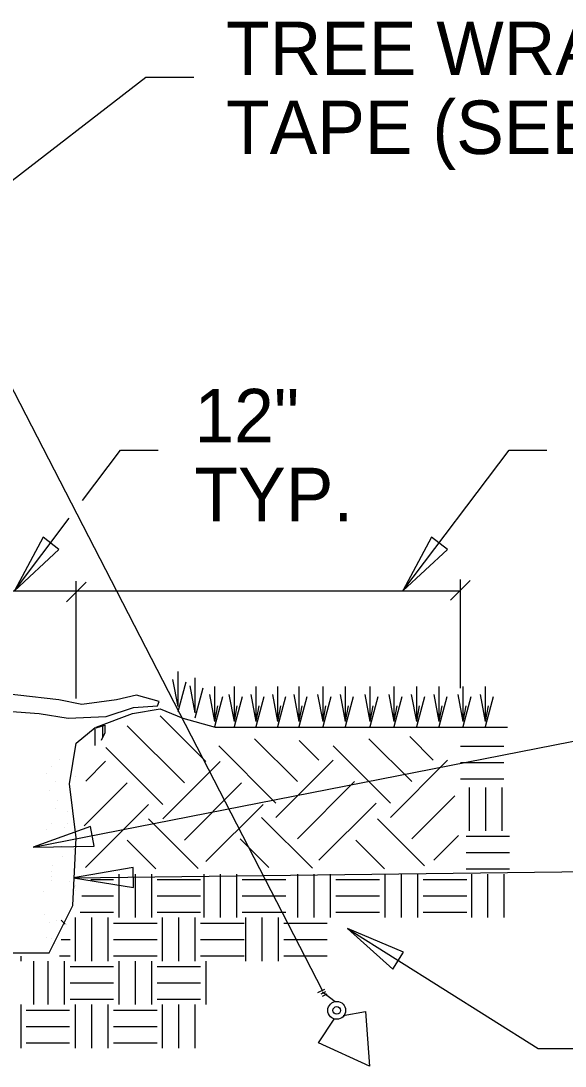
# Model space of a CAD drawing. Extents: x 10082 to 10241, y 10014 to 10069.
# Drawn here: x 10140.48 to 10147.61, y 10021.71 to 10035.4 of the extents above; entities that cross this region are included whole.
import ezdxf

# ---------------------------------------------------------------- set-up
doc = ezdxf.new("R2010")
doc.units = 0
for name, color, linetype in [('Default', 7, 'Continuous'), ('G-DETL-LINE', 7, 'Continuous'), ('G-DETL-OTLN', 7, 'Continuous'), ('G-DETL-PATT', 7, 'Continuous'), ('G-DETL-TEXT', 7, 'Continuous')]:
    doc.layers.add(name, color=color, linetype=linetype)

msp = doc.modelspace()

# ---------------------------------------------------------------- linework, layer by layer
at = {"layer": 'Default'}
for p, q in [((10137.692, 10031.254), (10142.113, 10034.665)), ((10142.113, 10034.665), (10142.742, 10034.665)), ((10141.285, 10029.12), (10141.783, 10029.78)), ((10141.783, 10029.78), (10142.277, 10029.78)), ((10145.484, 10027.939), (10146.875, 10029.78)), ((10146.875, 10029.78), (10147.369, 10029.78)), ((10140.393, 10027.939), (10141.11, 10028.888)), ((10141.204, 10026.527), (10141.204, 10028.065)), ((10146.108, 10027.818), (10146.366, 10028.075)), ((10141.075, 10027.795), (10141.333, 10028.053)), ((10141.64, 10027.938), (10146.237, 10027.938)), ((10141.451, 10025.911), (10141.451, 10026.147)), ((10141.462, 10026.146), (10141.579, 10026.179)), ((10141.552, 10026.024), (10141.552, 10026.171)), ((10141.579, 10026.179), (10141.579, 10026.079)), ((10140.64, 10024.579), (10147.95, 10026.014)), ((10141.579, 10026.079), (10141.528, 10025.977)), ((10140.882, 10025.632), (10140.882, 10025.632)), ((10140.98, 10025.725), (10140.98, 10025.725)), ((10140.812, 10025.543), (10140.812, 10025.543)), ((10141.124, 10025.479), (10141.124, 10025.479)), ((10141.195, 10025.512), (10141.195, 10025.512)), ((10140.853, 10025.322), (10140.853, 10025.322)), ((10140.927, 10025.436), (10140.927, 10025.436)), ((10140.951, 10025.198), (10140.951, 10025.198)), ((10140.928, 10025.081), (10140.928, 10025.081)), ((10141.09, 10025.053), (10141.09, 10025.053)), ((10140.813, 10024.814), (10140.813, 10024.814)), ((10140.883, 10024.885), (10140.883, 10024.885)), ((10141.055, 10024.836), (10141.055, 10024.836)), ((10141.082, 10024.892), (10141.082, 10024.892)), ((10141.188, 10024.777), (10141.188, 10024.777)), ((10141.196, 10024.765), (10141.196, 10024.765)), ((10141.011, 10024.596), (10141.011, 10024.596)), ((10141.167, 10024.544), (10141.167, 10024.544)), ((10141.029, 10024.455), (10141.029, 10024.455)), ((10140.878, 10024.259), (10140.878, 10024.259)), ((10140.888, 10024.335), (10140.888, 10024.335)), ((10141.166, 10024.178), (10148.614, 10024.272)), ((10141.18, 10024.306), (10141.18, 10024.306)), ((10140.883, 10024.138), (10140.883, 10024.138)), ((10140.885, 10024.203), (10140.885, 10024.203)), ((10141.116, 10024.131), (10141.116, 10024.131)), ((10140.778, 10024.002), (10140.778, 10024.002)), ((10141.184, 10024.06), (10141.184, 10024.06)), ((10141.197, 10024.017), (10141.197, 10024.017)), ((10141.198, 10024.083), (10141.198, 10024.083)), ((10140.783, 10023.698), (10140.783, 10023.698)), ((10141.108, 10023.712), (10141.108, 10023.712)), ((10140.849, 10023.589), (10140.849, 10023.589)), ((10140.941, 10023.619), (10140.941, 10023.619)), ((10141.056, 10023.574), (10141.006, 10023.625)), ((10141.076, 10023.566), (10141.076, 10023.566)), ((10144.758, 10023.515), (10147.257, 10021.943)), ((10140.814, 10023.4), (10140.814, 10023.4)), ((10140.884, 10023.39), (10140.884, 10023.39)), ((10140.922, 10023.319), (10140.922, 10023.319)), ((10147.257, 10021.943), (10148.043, 10021.943))]:
    msp.add_line(p, q, dxfattribs=at)
for points in [[(10140.976, 10028.481), (10140.769, 10028.641), (10140.393, 10027.939)], [(10146.067, 10028.481), (10145.86, 10028.641), (10145.484, 10027.939)], [(10141.437, 10024.596), (10141.389, 10024.853), (10140.64, 10024.579)], [(10141.952, 10024.051), (10141.951, 10024.313), (10141.166, 10024.178)], [(10145.351, 10022.983), (10145.491, 10023.204), (10144.758, 10023.515)]]:
    msp.add_lwpolyline(points, close=True, dxfattribs=at)
msp.add_lwpolyline([(10140.089, 10027.938), (10141.64, 10027.938)], dxfattribs=at)
at = {"layer": 'G-DETL-LINE'}
for p, q in [((10144.432, 10022.702), (10138.588, 10034.035)), ((10146.237, 10026.664), (10146.237, 10028.087)), ((10142.537, 10026.422), (10142.537, 10026.88)), ((10142.537, 10026.422), (10142.469, 10026.775)), ((10142.537, 10026.356), (10142.642, 10026.746)), ((10142.761, 10026.342), (10142.694, 10026.695)), ((10142.761, 10026.342), (10142.761, 10026.8)), ((10142.761, 10026.275), (10142.866, 10026.666)), ((10143.019, 10026.229), (10142.952, 10026.582)), ((10143.019, 10026.229), (10143.019, 10026.687)), ((10143.019, 10026.162), (10143.124, 10026.553)), ((10143.276, 10026.229), (10143.208, 10026.582)), ((10143.276, 10026.229), (10143.276, 10026.687)), ((10143.276, 10026.162), (10143.381, 10026.553)), ((10143.561, 10026.229), (10143.494, 10026.582)), ((10143.561, 10026.229), (10143.561, 10026.687)), ((10143.561, 10026.162), (10143.666, 10026.553)), ((10143.847, 10026.229), (10143.78, 10026.582)), ((10143.847, 10026.229), (10143.847, 10026.687)), ((10143.847, 10026.162), (10143.952, 10026.553)), ((10144.124, 10026.229), (10144.057, 10026.582)), ((10144.124, 10026.229), (10144.124, 10026.687)), ((10144.124, 10026.162), (10144.229, 10026.553)), ((10144.437, 10026.229), (10144.37, 10026.582)), ((10144.437, 10026.229), (10144.437, 10026.687)), ((10144.437, 10026.162), (10144.542, 10026.553)), ((10144.733, 10026.229), (10144.666, 10026.582)), ((10144.733, 10026.229), (10144.733, 10026.687)), ((10144.733, 10026.162), (10144.838, 10026.553)), ((10145.056, 10026.229), (10144.989, 10026.582)), ((10145.056, 10026.229), (10145.056, 10026.687)), ((10145.056, 10026.162), (10145.161, 10026.553)), ((10145.371, 10026.229), (10145.304, 10026.582)), ((10145.371, 10026.229), (10145.371, 10026.687)), ((10145.371, 10026.162), (10145.476, 10026.553)), ((10145.665, 10026.229), (10145.598, 10026.582)), ((10145.665, 10026.229), (10145.665, 10026.687)), ((10145.665, 10026.162), (10145.77, 10026.553)), ((10145.959, 10026.229), (10145.892, 10026.582)), ((10145.959, 10026.229), (10145.959, 10026.687)), ((10145.959, 10026.162), (10146.064, 10026.553)), ((10146.274, 10026.229), (10146.207, 10026.582)), ((10146.274, 10026.229), (10146.274, 10026.687)), ((10146.274, 10026.162), (10146.379, 10026.553)), ((10146.568, 10026.229), (10146.501, 10026.582)), ((10146.568, 10026.229), (10146.568, 10026.687)), ((10146.568, 10026.162), (10146.673, 10026.553)), ((10143.019, 10026.229), (10143.057, 10026.43)), ((10143.276, 10026.229), (10143.313, 10026.43)), ((10143.561, 10026.229), (10143.599, 10026.43)), ((10143.847, 10026.229), (10143.885, 10026.43)), ((10144.124, 10026.229), (10144.162, 10026.43)), ((10144.437, 10026.229), (10144.474, 10026.43)), ((10144.733, 10026.229), (10144.771, 10026.43)), ((10145.056, 10026.229), (10145.094, 10026.43)), ((10145.371, 10026.229), (10145.409, 10026.43)), ((10145.665, 10026.229), (10145.703, 10026.43)), ((10145.959, 10026.229), (10145.997, 10026.43)), ((10146.274, 10026.229), (10146.312, 10026.43)), ((10146.568, 10026.229), (10146.606, 10026.43))]:
    msp.add_line(p, q, dxfattribs=at)
for points in [[(10144.455, 10022.715), (10144.363, 10022.673)], [(10144.469, 10022.687), (10144.409, 10022.655)], [(10144.486, 10022.657), (10144.426, 10022.625)], [(10144.596, 10022.553), (10144.429, 10022.683)], [(10144.992, 10022.429), (10145.045, 10021.713), (10144.38, 10022.018), (10144.585, 10022.326)], [(10144.702, 10022.376), (10144.992, 10022.429)]]:
    msp.add_lwpolyline(points, dxfattribs=at)
for radius in [0.117, 0.0496]:
    msp.add_circle((10144.617, 10022.443), radius, dxfattribs=at)
at = {"layer": 'G-DETL-OTLN'}
msp.add_lwpolyline([(10137.79, 10026.949), (10137.829, 10026.709), (10138.486, 10026.629), (10138.905, 10026.59), (10139.723, 10026.451), (10140.178, 10026.371), (10140.716, 10026.332), (10141.095, 10026.271), (10141.593, 10026.291), (10141.953, 10026.41), (10142.27, 10026.431), (10142.29, 10026.49), (10141.993, 10026.57), (10141.732, 10026.51), (10141.274, 10026.451), (10140.976, 10026.51), (10140.439, 10026.57), (10139.941, 10026.629), (10139.403, 10026.75), (10138.786, 10026.75), (10138.208, 10026.869), (10138.008, 10026.929)], close=True, dxfattribs=at)
for points in [[(10141.462, 10026.152), (10141.942, 10026.333), (10142.302, 10026.393), (10142.602, 10026.272), (10143.025, 10026.152), (10146.855, 10026.152)], [(10133.44, 10026.21), (10133.674, 10025.943), (10133.717, 10025.633), (10133.762, 10025.145), (10133.717, 10024.702), (10133.762, 10024.26), (10133.805, 10023.684), (10133.983, 10023.462), (10134.56, 10023.241), (10135.8, 10023.198), (10138.013, 10023.198), (10140.849, 10023.198), (10141.158, 10023.817), (10141.203, 10024.702), (10141.115, 10025.412), (10141.203, 10025.943), (10141.451, 10026.147)]]:
    msp.add_lwpolyline(points, dxfattribs=at)
at = {"layer": 'G-DETL-PATT'}
for p, q in [((10142.901, 10025.703), (10142.303, 10026.301)), ((10142.62, 10025.422), (10141.87, 10026.171)), ((10145.882, 10025.721), (10145.573, 10026.03)), ((10142.339, 10025.14), (10141.592, 10025.887)), ((10143.82, 10025.159), (10143.071, 10025.908)), ((10144.101, 10025.44), (10143.539, 10026.002)), ((10144.383, 10025.721), (10144.126, 10025.978)), ((10145.32, 10025.159), (10144.57, 10025.908)), ((10145.601, 10025.44), (10145.039, 10026.002)), ((10146.238, 10025.905), (10146.808, 10025.905)), ((10141.328, 10025.447), (10141.586, 10025.706)), ((10142.339, 10024.953), (10143.089, 10025.703)), ((10143.82, 10024.971), (10144.57, 10025.721)), ((10145.32, 10024.971), (10146.07, 10025.721)), ((10146.238, 10025.692), (10146.808, 10025.692)), ((10146.238, 10025.478), (10146.808, 10025.478)), ((10141.308, 10024.859), (10141.87, 10025.422)), ((10142.62, 10024.672), (10143.37, 10025.422)), ((10144.101, 10024.69), (10144.851, 10025.44)), ((10146.357, 10024.794), (10146.357, 10025.364)), ((10146.571, 10024.794), (10146.571, 10025.364)), ((10146.785, 10024.794), (10146.785, 10025.364)), ((10145.601, 10024.69), (10146.163, 10025.252)), ((10141.326, 10024.315), (10142.152, 10025.14)), ((10142.901, 10024.391), (10143.651, 10025.14)), ((10144.383, 10024.409), (10145.132, 10025.159)), ((10142.802, 10024.303), (10142.152, 10024.953)), ((10144.299, 10024.305), (10143.633, 10024.971)), ((10145.767, 10024.337), (10145.151, 10024.953)), ((10142.245, 10024.297), (10141.87, 10024.672)), ((10143.727, 10024.315), (10143.352, 10024.69)), ((10145.244, 10024.297), (10144.869, 10024.672)), ((10145.888, 10024.41), (10146.211, 10024.734)), ((10146.312, 10024.723), (10146.882, 10024.723)), ((10146.312, 10024.509), (10146.882, 10024.509)), ((10141.764, 10023.658), (10141.764, 10024.229)), ((10141.978, 10023.658), (10141.978, 10024.229)), ((10142.192, 10023.658), (10142.192, 10024.229)), ((10142.879, 10023.658), (10142.879, 10024.229)), ((10143.093, 10023.658), (10143.093, 10024.229)), ((10143.307, 10023.658), (10143.307, 10024.229)), ((10144.107, 10023.658), (10144.107, 10024.229)), ((10144.321, 10023.658), (10144.321, 10024.229)), ((10144.535, 10023.658), (10144.535, 10024.229)), ((10145.251, 10023.658), (10145.251, 10024.229)), ((10145.465, 10023.658), (10145.465, 10024.229)), ((10145.678, 10023.658), (10145.678, 10024.229)), ((10146.312, 10024.295), (10146.882, 10024.295)), ((10146.386, 10023.658), (10146.386, 10024.229)), ((10146.599, 10023.658), (10146.599, 10024.229)), ((10146.813, 10023.658), (10146.813, 10024.229)), ((10141.394, 10024.157), (10141.692, 10024.157)), ((10142.263, 10024.157), (10142.833, 10024.157)), ((10143.378, 10024.157), (10143.948, 10024.157)), ((10144.606, 10024.157), (10145.177, 10024.157)), ((10145.75, 10024.157), (10146.32, 10024.157)), ((10141.276, 10023.944), (10141.692, 10023.944)), ((10142.263, 10023.944), (10142.833, 10023.944)), ((10143.378, 10023.944), (10143.948, 10023.944)), ((10144.606, 10023.944), (10145.177, 10023.944)), ((10145.75, 10023.944), (10146.32, 10023.944)), ((10141.255, 10023.73), (10141.692, 10023.73)), ((10142.263, 10023.73), (10142.833, 10023.73)), ((10143.378, 10023.73), (10143.948, 10023.73)), ((10144.606, 10023.73), (10145.177, 10023.73)), ((10145.75, 10023.73), (10146.32, 10023.73)), ((10141.193, 10023.088), (10141.193, 10023.658)), ((10141.407, 10023.088), (10141.407, 10023.658)), ((10141.621, 10023.088), (10141.621, 10023.658)), ((10141.692, 10023.587), (10142.263, 10023.587)), ((10142.334, 10023.088), (10142.334, 10023.658)), ((10142.548, 10023.088), (10142.548, 10023.658)), ((10142.762, 10023.088), (10142.762, 10023.658)), ((10142.833, 10023.587), (10143.404, 10023.587)), ((10143.424, 10023.088), (10143.424, 10023.658)), ((10143.638, 10023.088), (10143.638, 10023.658)), ((10143.852, 10023.088), (10143.852, 10023.658)), ((10143.923, 10023.587), (10144.493, 10023.587)), ((10141.004, 10023.373), (10141.122, 10023.373)), ((10141.692, 10023.373), (10142.263, 10023.373)), ((10142.833, 10023.373), (10143.404, 10023.373)), ((10143.923, 10023.373), (10144.493, 10023.373)), ((10140.48, 10023.088), (10140.48, 10023.151)), ((10140.983, 10023.159), (10141.122, 10023.159)), ((10141.692, 10023.159), (10142.263, 10023.159)), ((10142.833, 10023.159), (10143.404, 10023.159)), ((10143.923, 10023.159), (10144.493, 10023.159)), ((10140.647, 10022.518), (10140.647, 10023.088)), ((10140.837, 10022.518), (10140.837, 10023.088)), ((10141.051, 10022.518), (10141.051, 10023.088)), ((10141.122, 10023.017), (10141.692, 10023.017)), ((10141.764, 10022.518), (10141.764, 10023.088)), ((10141.978, 10022.518), (10141.978, 10023.088)), ((10142.192, 10022.518), (10142.192, 10023.088)), ((10142.263, 10023.017), (10142.833, 10023.017)), ((10142.905, 10022.518), (10142.905, 10023.088)), ((10141.122, 10022.803), (10141.692, 10022.803)), ((10142.263, 10022.803), (10142.833, 10022.803)), ((10141.122, 10022.589), (10141.692, 10022.589)), ((10142.263, 10022.589), (10142.833, 10022.589)), ((10140.48, 10021.947), (10140.48, 10022.518)), ((10140.546, 10022.446), (10141.116, 10022.446)), ((10141.193, 10021.947), (10141.193, 10022.518)), ((10141.407, 10021.947), (10141.407, 10022.518)), ((10141.621, 10021.947), (10141.621, 10022.518)), ((10141.692, 10022.446), (10142.263, 10022.446)), ((10142.334, 10021.947), (10142.334, 10022.518)), ((10142.548, 10021.947), (10142.548, 10022.518)), ((10142.762, 10021.947), (10142.762, 10022.518)), ((10140.546, 10022.232), (10141.116, 10022.232)), ((10141.692, 10022.232), (10142.263, 10022.232)), ((10140.546, 10022.018), (10141.116, 10022.018)), ((10141.692, 10022.018), (10142.263, 10022.018))]:
    msp.add_line(p, q, dxfattribs=at)

# ---------------------------------------------------------------- texts
at = {"layer": 'G-DETL-TEXT'}
for s, p in [('TREE WRAP SECURED WITH ', (10143.166, 10034.693)), ('TAPE (SEE SPECIFICATIONS)', (10143.166, 10033.66)), ('12" ', (10142.752, 10029.883)), ('TYP.', (10142.752, 10028.85))]:
    msp.add_text(s, height=0.7, dxfattribs=at).set_placement(p)

doc.saveas('drawing.dxf')
